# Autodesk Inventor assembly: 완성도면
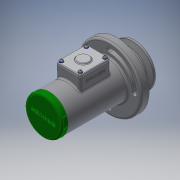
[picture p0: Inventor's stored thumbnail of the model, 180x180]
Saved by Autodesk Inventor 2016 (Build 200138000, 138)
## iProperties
Created: 2017-05
Part Number: 완성도면
Material: 일반
Document SubType Name: Assembly
Designer: USER
Author: USER
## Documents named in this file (20)
- C:\Users\USER\Desktop\470508V1012\완성도면.iam
- C:\Users\USER\Desktop\470508V1012\본체.ipt
- C:\Users\USER\Desktop\470508V1012\V-벨트풀리.ipt
- C:\Users\USER\Desktop\470508V1012\너트 M10.ipt
- C:\Users\USER\Desktop\470508V1012\멈춤링 15 x 1.ipt
- C:\Users\USER\Desktop\470508V1012\멈춤링 35x1.6.ipt
- C:\Users\USER\Desktop\470508V1012\베어링 15 x 35 x 11.ipt
- C:\Users\USER\Desktop\470508V1012\볼트 M4 x 10.ipt
- C:\Users\USER\Desktop\470508V1012\부시1.ipt
- C:\Users\USER\Desktop\470508V1012\부시2.ipt
- C:\Users\USER\Desktop\470508V1012\사이드 커버.ipt
- 사이드 커버.ipt
- C:\Users\USER\Desktop\470508V1012\십자볼트 M3 x 10.ipt
- C:\Users\USER\Desktop\470508V1012\오일 실 15 25 7.ipt
- C:\Users\USER\Desktop\470508V1012\와셔 3x6.ipt
- C:\Users\USER\Desktop\470508V1012\와셔 4x16.ipt
- C:\Users\USER\Desktop\470508V1012\와셔 10x21.ipt
- C:\Users\USER\Desktop\470508V1012\축.ipt
- C:\Users\USER\Desktop\470508V1012\키 4 x 4 x 18.ipt
- C:\Users\USER\Desktop\470508V1012\탑 커버.ipt
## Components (2 placed, 2 different names)
1. V-벨트풀리:1
2. ISO 4017 M4 x 10:1
